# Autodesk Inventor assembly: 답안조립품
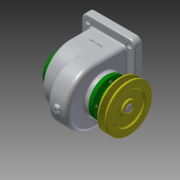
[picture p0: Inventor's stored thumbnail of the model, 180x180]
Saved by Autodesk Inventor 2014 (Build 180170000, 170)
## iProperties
Created: 2017-11
Part Number: 답안조립품
Document SubType Name: Assembly
Designer: user
Author: user
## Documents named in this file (14)
- C:\Users\user\Desktop\471108V1003\답안조립품.iam
- C:\Users\user\Desktop\471108V1003\축.ipt
- C:\Users\user\Desktop\471108V1003\키 - 5 x 5 x 18.ipt
- C:\Users\user\Desktop\471108V1003\키 - 6 x 6 x 22.ipt
- C:\Users\user\Desktop\471108V1003\V-벨트풀리.ipt
- C:\Users\user\Desktop\471108V1003\멈춤나사 - M4 x 10.ipt
- 멈춤나사 - M4 x 10.ipt
- C:\Users\user\Desktop\471108V1003\스퍼기어.ipt
- C:\Users\user\Desktop\471108V1003\베어링 6002.ipt
- C:\Users\user\Desktop\471108V1003\앞커버.ipt
- C:\Users\user\Desktop\471108V1003\오일 실 15 30 7.ipt
- C:\Users\user\Desktop\471108V1003\뒤커버.ipt
- C:\Users\user\Desktop\471108V1003\본체.ipt
- C:\Users\user\Desktop\471108V1003\볼트 M3 x 8.ipt
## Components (1 placed, 1 different names)
1. V-벨트풀리:1 — 각도:1
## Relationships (1: Angle 1)
- 각도:1 [Angle]: V-벨트풀리:1
